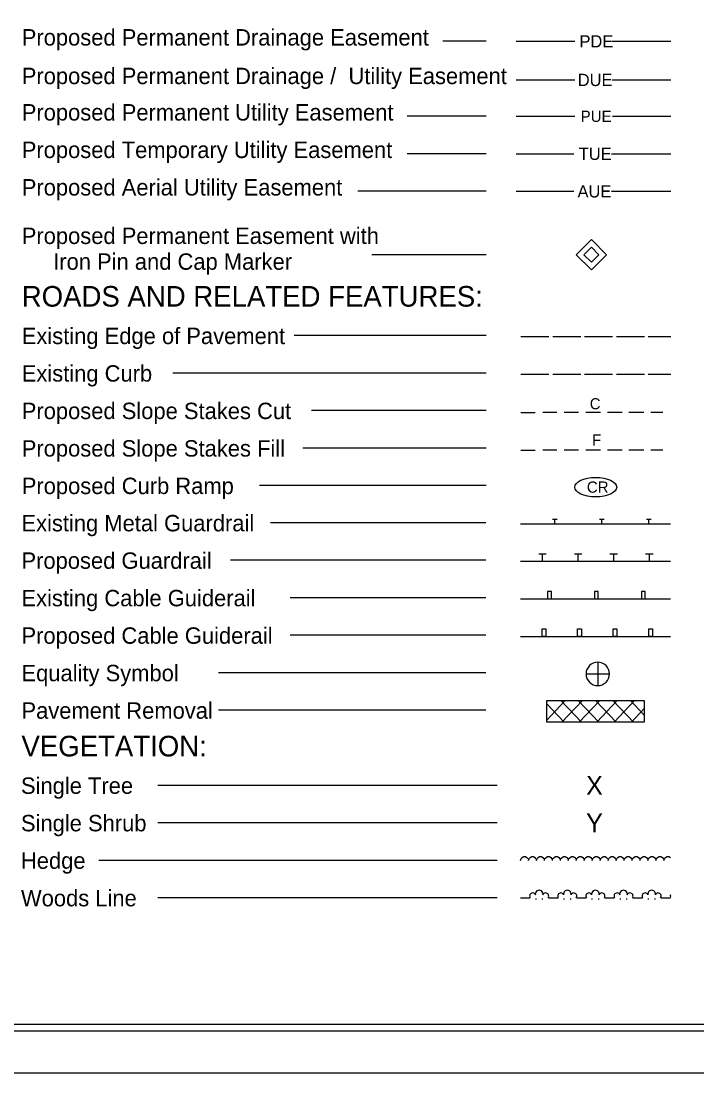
# Model space of a CAD drawing. Extents: x 1513414 to 1532852, y 643392 to 657912.
# Drawn here: x 1528586 to 1528947, y 643392 to 643953 of the extents above; entities that cross this region are included whole.
import ezdxf

# ---------------------------------------------------------------- set-up
doc = ezdxf.new("R2010")
doc.units = 0
for name, color, linetype in [('Prop Easement Permanent Drainage Utility', 7, 'Continuous'), ('Prop ROW Permanent Easement CELL', 7, 'Continuous'), ('Prop Shade Light', 7, 'Continuous'), ('Prop WCC CELL', 7, 'Continuous'), ('Sheet Cutting Line CELL', 7, 'Continuous'), ('Sheet Plot Border Inside CELL', 7, 'Continuous'), ('Sheet Plot Border Outside CELL', 7, 'Continuous'), ('Sheet Symbology CELL', 7, 'Continuous')]:
    doc.layers.add(name, color=color, linetype=linetype)

# ---------------------------------------------------------------- blocks, each defined once
blk = doc.blocks.new('EQCIR')
at = {"layer": 'Sheet Symbology CELL'}
for p, q in [((0, 0.25), (0, 0)), ((-0.25, 0), (0, 0)), ((0, 0), (0, -0.25)), ((0, 0), (0.25, 0))]:
    blk.add_line(p, q, dxfattribs=at)
for start, end in [(89.9944, 179.9989), (359.9944, 89.9989), (179.9944, 269.9989), (269.9944, 359.9989)]:
    blk.add_arc((0, 0), 0.25, start, end, dxfattribs=at)
blk = doc.blocks.new('ROW Marker Permanent Easement-E')
at = {"layer": 'Prop ROW Permanent Easement CELL'}
blk.add_line((0, 0), (0, 0), dxfattribs=at)
for points in [[(0, 0.072), (0.072, 0), (0, -0.072), (-0.072, 0)], [(0, 0.036), (0.036, 0), (0, -0.036), (-0.036, 0)]]:
    blk.add_lwpolyline(points, close=True, dxfattribs=at)
blk = doc.blocks.new('CR')
at = {"layer": 'Prop WCC CELL'}
blk.add_ellipse((0.02, -0.02), major_axis=(5.61, 0), ratio=0.462467, dxfattribs=at)
blk.add_text('CR', height=3, dxfattribs=at).set_placement((-2.34, -1.5))

msp = doc.modelspace()

# ---------------------------------------------------------------- linework, layer by layer
at = {"layer": 'Prop Easement Permanent Drainage Utility'}
for p, q in [((1528850.11, 643921.37), (1528881.41, 643921.37)), ((1528901.41, 643921.37), (1528932.61, 643921.37))]:
    msp.add_line(p, q, dxfattribs=at)
at = {"layer": 'Sheet Cutting Line CELL'}
msp.add_line((1528024.61, 643391.59), (1529708.61, 643391.59), dxfattribs=at)
at = {"layer": 'Sheet Plot Border Inside CELL'}
msp.add_lwpolyline([(1528037.61, 643414.04), (1529704.11, 643414.04), (1529704.11, 644469.14), (1528037.61, 644469.14)], close=True, dxfattribs=at)
at = {"layer": 'Sheet Plot Border Outside CELL'}
msp.add_lwpolyline([(1528024.61, 643391.59), (1529708.61, 643391.59), (1529708.61, 644491.59), (1528024.61, 644491.59)], close=True, dxfattribs=at)
at = {"layer": 'Sheet Symbology CELL'}
for p, q in [((1528834.08, 643941.95), (1528810.93, 643941.95)), ((1528850.11, 643941.95), (1528853.91, 643941.95)), ((1528853.91, 643941.95), (1528881.41, 643941.95)), ((1528901.41, 643941.95), (1528928.91, 643941.95)), ((1528928.91, 643941.95), (1528932.61, 643941.95)), ((1528834.08, 643901.94), (1528791.94, 643901.94)), ((1528850.11, 643901.94), (1528853.94, 643901.94)), ((1528853.94, 643901.94), (1528881.44, 643901.94)), ((1528901.44, 643901.94), (1528928.94, 643901.94)), ((1528928.94, 643901.94), (1528932.61, 643901.94)), ((1528834.08, 643881.94), (1528791.94, 643881.94)), ((1528850.11, 643881.94), (1528853.46, 643881.94)), ((1528853.46, 643881.94), (1528880.96, 643881.94)), ((1528900.96, 643881.94), (1528928.46, 643881.94)), ((1528928.46, 643881.94), (1528932.61, 643881.94)), ((1528834.08, 643861.94), (1528765.62, 643861.94)), ((1528850.11, 643861.94), (1528853.46, 643861.94)), ((1528853.46, 643861.94), (1528880.96, 643861.94)), ((1528900.96, 643861.94), (1528928.46, 643861.94)), ((1528928.46, 643861.94), (1528932.61, 643861.94)), ((1528834.08, 643828.12), (1528773.07, 643828.12)), ((1528834.08, 643784.96), (1528731.73, 643784.96)), ((1528852.61, 643784.39), (1528867.61, 643784.39)), ((1528869.61, 643784.39), (1528884.61, 643784.39)), ((1528886.61, 643784.39), (1528901.61, 643784.39)), ((1528903.61, 643784.39), (1528918.61, 643784.39)), ((1528920.61, 643784.39), (1528932.61, 643784.39)), ((1528834.08, 643764.96), (1528666.93, 643764.96)), ((1528852.61, 643764.39), (1528867.61, 643764.39)), ((1528869.61, 643764.39), (1528884.61, 643764.39)), ((1528886.61, 643764.39), (1528901.61, 643764.39)), ((1528903.61, 643764.39), (1528918.61, 643764.39)), ((1528920.61, 643764.39), (1528932.61, 643764.39)), ((1528834.08, 643744.96), (1528740.89, 643744.96)), ((1528852.61, 643743.91), (1528860.21, 643743.91)), ((1528871.91, 643743.91), (1528864.36, 643743.91)), ((1528883.41, 643743.91), (1528875.81, 643743.91)), ((1528895.16, 643743.91), (1528887.36, 643743.91)), ((1528906.61, 643743.91), (1528898.86, 643743.91)), ((1528918.16, 643743.91), (1528910.31, 643743.91)), ((1528928.46, 643743.91), (1528922.06, 643743.91)), ((1528834.08, 643724.96), (1528736.34, 643724.96)), ((1528852.61, 643723.91), (1528860.21, 643723.91)), ((1528871.91, 643723.91), (1528864.36, 643723.91)), ((1528883.41, 643723.91), (1528875.81, 643723.91)), ((1528895.16, 643723.91), (1528887.36, 643723.91)), ((1528906.61, 643723.91), (1528898.86, 643723.91)), ((1528918.16, 643723.91), (1528910.31, 643723.91)), ((1528928.46, 643723.91), (1528922.06, 643723.91)), ((1528834.08, 643704.96), (1528713.15, 643704.96)), ((1528833.92, 643685.08), (1528719.08, 643685.08)), ((1528852.45, 643684.51), (1528932.45, 643684.51)), ((1528869.59, 643687.01), (1528872.09, 643687.01)), ((1528870.84, 643684.51), (1528870.84, 643687.01)), ((1528894.59, 643687.01), (1528897.09, 643687.01)), ((1528895.84, 643684.51), (1528895.84, 643687.01)), ((1528919.59, 643687.01), (1528922.09, 643687.01)), ((1528920.84, 643684.51), (1528920.84, 643687.01)), ((1528862.18, 643668.46), (1528866.18, 643668.46)), ((1528864.18, 643664.51), (1528864.18, 643668.46)), ((1528881.18, 643668.46), (1528885.18, 643668.46)), ((1528883.18, 643664.51), (1528883.18, 643668.46)), ((1528900.18, 643668.46), (1528904.18, 643668.46)), ((1528902.18, 643664.51), (1528902.18, 643668.46)), ((1528919.18, 643668.46), (1528923.18, 643668.46)), ((1528921.18, 643664.51), (1528921.18, 643668.46)), ((1528833.92, 643665.08), (1528697.68, 643665.08)), ((1528932.45, 643664.51), (1528852.45, 643664.51)), ((1528833.92, 643645.08), (1528729.62, 643645.08)), ((1528852.45, 643644.51), (1528932.45, 643644.51)), ((1528833.92, 643625.08), (1528729.62, 643625.08)), ((1528852.45, 643624.51), (1528932.45, 643624.51)), ((1528833.92, 643605.08), (1528691.3, 643605.08)), ((1528866.4, 643590.37), (1528918.5, 643590.37)), ((1528866.4, 643578.67), (1528866.4, 643590.37)), ((1528866.4, 643589.77), (1528866.95, 643590.37)), ((1528866.4, 643579.82), (1528876.25, 643590.37)), ((1528875.65, 643578.67), (1528866.4, 643588.57)), ((1528884.95, 643578.67), (1528873.95, 643590.37)), ((1528874.55, 643578.67), (1528885.55, 643590.37)), ((1528894.2, 643578.67), (1528883.25, 643590.37)), ((1528883.8, 643578.67), (1528894.85, 643590.37)), ((1528903.5, 643578.67), (1528892.5, 643590.37)), ((1528893.1, 643578.67), (1528904.1, 643590.37)), ((1528912.8, 643578.67), (1528901.75, 643590.37)), ((1528902.4, 643578.67), (1528913.35, 643590.37)), ((1528918.5, 643582.42), (1528911.05, 643590.37)), ((1528918.5, 643590.37), (1528918.5, 643578.67)), ((1528833.92, 643585.08), (1528691.3, 643585.08)), ((1528911.65, 643578.67), (1528918.5, 643585.97)), ((1528918.5, 643578.67), (1528866.4, 643578.67)), ((1528840.06, 643545.01), (1528658.93, 643545.01)), ((1528840.06, 643525.01), (1528658.93, 643525.01)), ((1528840.06, 643505.01), (1528627.37, 643505.01)), ((1528852.45, 643505.01), (1528852.75, 643505.96)), ((1528852.75, 643505.96), (1528853.35, 643506.61)), ((1528853.35, 643506.61), (1528854.15, 643507.06)), ((1528854.15, 643507.06), (1528855.1, 643507.06)), ((1528855.1, 643507.06), (1528855.9, 643506.56)), ((1528855.9, 643506.56), (1528856.45, 643505.91)), ((1528856.45, 643505.91), (1528856.65, 643505.06)), ((1528856.7, 643505.01), (1528857, 643505.96)), ((1528857, 643505.96), (1528857.6, 643506.61)), ((1528857.6, 643506.61), (1528858.4, 643507.06)), ((1528858.4, 643507.06), (1528859.35, 643507.06)), ((1528859.35, 643507.06), (1528860.15, 643506.56)), ((1528860.15, 643506.56), (1528860.7, 643505.91)), ((1528860.7, 643505.91), (1528860.9, 643505.06)), ((1528860.95, 643505.01), (1528861.25, 643505.96)), ((1528861.25, 643505.96), (1528861.85, 643506.61)), ((1528861.85, 643506.61), (1528862.65, 643507.06)), ((1528862.65, 643507.06), (1528863.6, 643507.06)), ((1528863.6, 643507.06), (1528864.4, 643506.56)), ((1528864.4, 643506.56), (1528864.95, 643505.91)), ((1528864.95, 643505.91), (1528865.15, 643505.06)), ((1528865.2, 643505.01), (1528865.5, 643505.96)), ((1528865.5, 643505.96), (1528866.1, 643506.61)), ((1528866.1, 643506.61), (1528866.9, 643507.06)), ((1528866.9, 643507.06), (1528867.85, 643507.06)), ((1528867.85, 643507.06), (1528868.65, 643506.56)), ((1528868.65, 643506.56), (1528869.2, 643505.91)), ((1528869.2, 643505.91), (1528869.4, 643505.06)), ((1528869.45, 643505.01), (1528869.75, 643505.96)), ((1528869.75, 643505.96), (1528870.35, 643506.61)), ((1528870.35, 643506.61), (1528871.15, 643507.06)), ((1528871.15, 643507.06), (1528872.1, 643507.06)), ((1528872.1, 643507.06), (1528872.9, 643506.56)), ((1528872.9, 643506.56), (1528873.45, 643505.91)), ((1528873.45, 643505.91), (1528873.65, 643505.06)), ((1528873.7, 643505.01), (1528874, 643505.96)), ((1528874, 643505.96), (1528874.6, 643506.61)), ((1528874.6, 643506.61), (1528875.4, 643507.06)), ((1528875.4, 643507.06), (1528876.35, 643507.06)), ((1528876.35, 643507.06), (1528877.15, 643506.56)), ((1528877.15, 643506.56), (1528877.7, 643505.91)), ((1528877.7, 643505.91), (1528877.9, 643505.06)), ((1528877.95, 643505.01), (1528878.25, 643505.96)), ((1528878.25, 643505.96), (1528878.85, 643506.61)), ((1528878.85, 643506.61), (1528879.65, 643507.06)), ((1528879.65, 643507.06), (1528880.6, 643507.06)), ((1528880.6, 643507.06), (1528881.4, 643506.56)), ((1528881.4, 643506.56), (1528881.95, 643505.91)), ((1528881.95, 643505.91), (1528882.15, 643505.06)), ((1528882.2, 643505.01), (1528882.5, 643505.96)), ((1528882.5, 643505.96), (1528883.1, 643506.61)), ((1528883.1, 643506.61), (1528883.9, 643507.06)), ((1528883.9, 643507.06), (1528884.85, 643507.06)), ((1528884.85, 643507.06), (1528885.65, 643506.56)), ((1528885.65, 643506.56), (1528886.2, 643505.91)), ((1528886.2, 643505.91), (1528886.4, 643505.06)), ((1528886.45, 643505.01), (1528886.75, 643505.96)), ((1528886.75, 643505.96), (1528887.35, 643506.61)), ((1528887.35, 643506.61), (1528888.15, 643507.06)), ((1528888.15, 643507.06), (1528889.1, 643507.06)), ((1528889.1, 643507.06), (1528889.9, 643506.56)), ((1528889.9, 643506.56), (1528890.45, 643505.91)), ((1528890.45, 643505.91), (1528890.65, 643505.06)), ((1528890.7, 643505.01), (1528891, 643505.96)), ((1528891, 643505.96), (1528891.6, 643506.61)), ((1528891.6, 643506.61), (1528892.4, 643507.06)), ((1528892.4, 643507.06), (1528893.35, 643507.06)), ((1528893.35, 643507.06), (1528894.15, 643506.56)), ((1528894.15, 643506.56), (1528894.7, 643505.91)), ((1528894.7, 643505.91), (1528894.9, 643505.06)), ((1528894.95, 643505.01), (1528895.25, 643505.96)), ((1528895.25, 643505.96), (1528895.85, 643506.61)), ((1528895.85, 643506.61), (1528896.65, 643507.06)), ((1528896.65, 643507.06), (1528897.6, 643507.06)), ((1528897.6, 643507.06), (1528898.4, 643506.56)), ((1528898.4, 643506.56), (1528898.95, 643505.91)), ((1528898.95, 643505.91), (1528899.15, 643505.06)), ((1528899.2, 643505.01), (1528899.5, 643505.96)), ((1528899.5, 643505.96), (1528900.1, 643506.61)), ((1528900.1, 643506.61), (1528900.9, 643507.06)), ((1528900.9, 643507.06), (1528901.85, 643507.06)), ((1528901.85, 643507.06), (1528902.65, 643506.56)), ((1528902.65, 643506.56), (1528903.2, 643505.91)), ((1528903.2, 643505.91), (1528903.4, 643505.06)), ((1528903.45, 643505.01), (1528903.75, 643505.96)), ((1528903.75, 643505.96), (1528904.35, 643506.61)), ((1528904.35, 643506.61), (1528905.15, 643507.06)), ((1528905.15, 643507.06), (1528906.1, 643507.06)), ((1528906.1, 643507.06), (1528906.9, 643506.56)), ((1528906.9, 643506.56), (1528907.45, 643505.91)), ((1528907.45, 643505.91), (1528907.65, 643505.06)), ((1528907.7, 643505.01), (1528908, 643505.96)), ((1528908, 643505.96), (1528908.6, 643506.61)), ((1528908.6, 643506.61), (1528909.4, 643507.06)), ((1528909.4, 643507.06), (1528910.35, 643507.06)), ((1528910.35, 643507.06), (1528911.15, 643506.56)), ((1528911.15, 643506.56), (1528911.7, 643505.91)), ((1528911.7, 643505.91), (1528911.9, 643505.06)), ((1528911.95, 643505.01), (1528912.25, 643505.96)), ((1528912.25, 643505.96), (1528912.85, 643506.61)), ((1528912.85, 643506.61), (1528913.65, 643507.06)), ((1528913.65, 643507.06), (1528914.6, 643507.06)), ((1528914.6, 643507.06), (1528915.4, 643506.56)), ((1528915.4, 643506.56), (1528915.95, 643505.91)), ((1528915.95, 643505.91), (1528916.15, 643505.06)), ((1528916.2, 643505.01), (1528916.5, 643505.96)), ((1528916.5, 643505.96), (1528917.1, 643506.61)), ((1528917.1, 643506.61), (1528917.9, 643507.06)), ((1528917.9, 643507.06), (1528918.85, 643507.06)), ((1528918.85, 643507.06), (1528919.65, 643506.56)), ((1528919.65, 643506.56), (1528920.2, 643505.91)), ((1528920.2, 643505.91), (1528920.4, 643505.06)), ((1528920.45, 643505.01), (1528920.75, 643505.96)), ((1528920.75, 643505.96), (1528921.35, 643506.61)), ((1528921.35, 643506.61), (1528922.15, 643507.06)), ((1528922.15, 643507.06), (1528923.1, 643507.06)), ((1528923.1, 643507.06), (1528923.9, 643506.56)), ((1528923.9, 643506.56), (1528924.45, 643505.91)), ((1528924.45, 643505.91), (1528924.65, 643505.06)), ((1528924.7, 643505.01), (1528925, 643505.96)), ((1528925, 643505.96), (1528925.6, 643506.61)), ((1528925.6, 643506.61), (1528926.4, 643507.06)), ((1528926.4, 643507.06), (1528927.35, 643507.06)), ((1528927.35, 643507.06), (1528928.15, 643506.56)), ((1528928.15, 643506.56), (1528928.7, 643505.91)), ((1528928.7, 643505.91), (1528928.9, 643505.06)), ((1528928.95, 643505.01), (1528929.25, 643505.96)), ((1528929.25, 643505.96), (1528929.85, 643506.61)), ((1528929.85, 643506.61), (1528930.65, 643507.06)), ((1528930.65, 643507.06), (1528931.6, 643507.06)), ((1528931.6, 643507.06), (1528932.4, 643506.56)), ((1528932.4, 643506.56), (1528932.45, 643506.51)), ((1528840.06, 643485.01), (1528658.93, 643485.01)), ((1528852.45, 643485.01), (1528857.45, 643485.01)), ((1528860.4, 643484.51), (1528860.9, 643484.51)), ((1528863.9, 643484.51), (1528864.4, 643484.51)), ((1528867.45, 643485.01), (1528872.45, 643485.01)), ((1528875.4, 643484.51), (1528875.9, 643484.51)), ((1528878.9, 643484.51), (1528879.4, 643484.51)), ((1528882.45, 643485.01), (1528887.45, 643485.01)), ((1528890.4, 643484.51), (1528890.9, 643484.51)), ((1528893.9, 643484.51), (1528894.4, 643484.51)), ((1528897.45, 643485.01), (1528902.45, 643485.01)), ((1528905.4, 643484.51), (1528905.9, 643484.51)), ((1528908.9, 643484.51), (1528909.4, 643484.51)), ((1528912.45, 643485.01), (1528917.45, 643485.01)), ((1528920.4, 643484.51), (1528920.9, 643484.51)), ((1528923.9, 643484.51), (1528924.4, 643484.51)), ((1528927.45, 643485.01), (1528932.45, 643485.01))]:
    msp.add_line(p, q, dxfattribs=at)
for points in [[(1529691.61, 644466.59), (1528191.61, 644466.59), (1528191.61, 643417.61), (1529691.61, 643417.61)], [(1528866.93, 643644.51), (1528868.93, 643644.51), (1528868.93, 643648.51), (1528866.93, 643648.51)], [(1528891.93, 643644.51), (1528893.93, 643644.51), (1528893.93, 643648.51), (1528891.93, 643648.51)], [(1528916.93, 643644.51), (1528918.93, 643644.51), (1528918.93, 643648.51), (1528916.93, 643648.51)], [(1528863.91, 643628.51), (1528865.91, 643628.51), (1528865.91, 643624.51), (1528863.91, 643624.51)], [(1528882.91, 643628.51), (1528884.91, 643628.51), (1528884.91, 643624.51), (1528882.91, 643624.51)], [(1528901.91, 643628.51), (1528903.91, 643628.51), (1528903.91, 643624.51), (1528901.91, 643624.51)], [(1528920.91, 643628.51), (1528922.91, 643628.51), (1528922.91, 643624.51), (1528920.91, 643624.51)]]:
    msp.add_lwpolyline(points, close=True, dxfattribs=at)
for centre, radius, start, end in [((1528858.9, 643486.03), 1.58, 18.435, 219.2315), ((1528862.4, 643487.03), 2.06, 345.9638, 194.0362), ((1528865.9, 643486.03), 1.58, 320.7685, 161.5651), ((1528873.9, 643486.03), 1.58, 18.435, 219.2315), ((1528877.4, 643487.03), 2.06, 345.9638, 194.0362), ((1528880.9, 643486.03), 1.58, 320.7685, 161.5651), ((1528888.9, 643486.03), 1.58, 18.435, 219.2315), ((1528892.4, 643487.03), 2.06, 345.9638, 194.0362), ((1528895.9, 643486.03), 1.58, 320.7685, 161.5651), ((1528903.9, 643486.03), 1.58, 18.435, 219.2315), ((1528907.4, 643487.03), 2.06, 345.9638, 194.0362), ((1528910.9, 643486.03), 1.58, 320.7685, 161.5651), ((1528918.9, 643486.03), 1.58, 18.435, 219.2315), ((1528922.4, 643487.03), 2.06, 345.9638, 194.0362), ((1528925.9, 643486.03), 1.58, 320.7685, 161.5651), ((1528933.9, 643486.03), 1.58, 156.251, 203.749)]:
    msp.add_arc(centre, radius, start, end, dxfattribs=at)

# ---------------------------------------------------------------- block references
at = {"layer": 'Prop Shade Light', "xscale": 25, "yscale": 25}
msp.add_blockref('EQCIR', (1528893.68, 643604.5), dxfattribs=at)
at = {"layer": 'Sheet Symbology CELL'}
for name, p, xscale, yscale in [('ROW Marker Permanent Easement-E', (1528890.25, 643828.12), 111.83773267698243, 111.83773267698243), ('CR', (1528892.53, 643704.14), 2, 2)]:
    msp.add_blockref(name, p, dxfattribs=dict(at, xscale=xscale, yscale=yscale))

# ---------------------------------------------------------------- texts
at = {"layer": 'Prop Easement Permanent Drainage Utility'}
msp.add_text('DUE', height=6.55, dxfattribs=at).set_placement((1528883, 643918.07))
at = {"layer": 'Sheet Symbology CELL'}
for s, height, p in [('Proposed Permanent Drainage Easement', 8.75, (1528586.33, 643939.69)), ('PDE', 6.55, (1528883.91, 643938.65)), ('Proposed Permanent Drainage /  Utility Easement', 8.75, (1528586.33, 643919.11)), ('Proposed Permanent Utility Easement', 8.75, (1528586.33, 643899.68)), ('PUE', 6, (1528884.54, 643898.94)), ('Proposed Temporary Utility Easement', 8.75, (1528586.33, 643879.68)), ('TUE', 6.55, (1528883.54, 643878.64)), ('Proposed Aerial Utility Easement', 8.75, (1528586.33, 643859.68)), ('AUE', 6.55, (1528882.88, 643858.64)), ('Proposed Permanent Easement with', 8.75, (1528586.33, 643833.82)), ('Iron Pin and Cap Marker', 8.75, (1528603.09, 643820.07)), ('ROADS AND RELATED FEATURES:', 11, (1528586.33, 643800.41)), ('Existing Edge of Pavement', 8.75, (1528586.33, 643780.41)), ('Existing Curb', 8.75, (1528586.33, 643760.41)), ('C', 5.93, (1528889.41, 643745.65)), ('Proposed Slope Stakes Cut', 8.75, (1528586.33, 643740.41)), ('Proposed Slope Stakes Fill', 8.75, (1528586.33, 643720.41)), ('F', 5.93, (1528890.61, 643726.28)), ('Proposed Curb Ramp', 8.75, (1528586.33, 643700.41)), ('Existing Metal Guardrail', 8.75, (1528586.17, 643680.53)), ('Proposed Guardrail', 8.75, (1528586.18, 643660.55)), ('Existing Cable Guiderail', 8.75, (1528586.18, 643640.55)), ('Proposed Cable Guiderail', 8.75, (1528586.18, 643620.55)), ('Equality Symbol', 8.75, (1528586.18, 643600.55)), ('Pavement Removal', 8.75, (1528586.18, 643580.55)), ('VEGETATION:', 11, (1528586.17, 643560.46)), ('Single Tree', 8.75, (1528585.9, 643540.49)), ('X', 10, (1528887.45, 643540.01)), ('Single Shrub', 8.75, (1528585.9, 643520.49)), ('Y', 10, (1528887.45, 643520.01)), ('Hedge', 8.75, (1528585.9, 643500.49)), ('Woods Line', 8.75, (1528585.9, 643480.49))]:
    msp.add_text(s, height=height, dxfattribs=at).set_placement(p)

doc.saveas('drawing.dxf')
